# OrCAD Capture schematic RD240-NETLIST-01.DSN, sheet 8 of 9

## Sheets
8 2: size A3
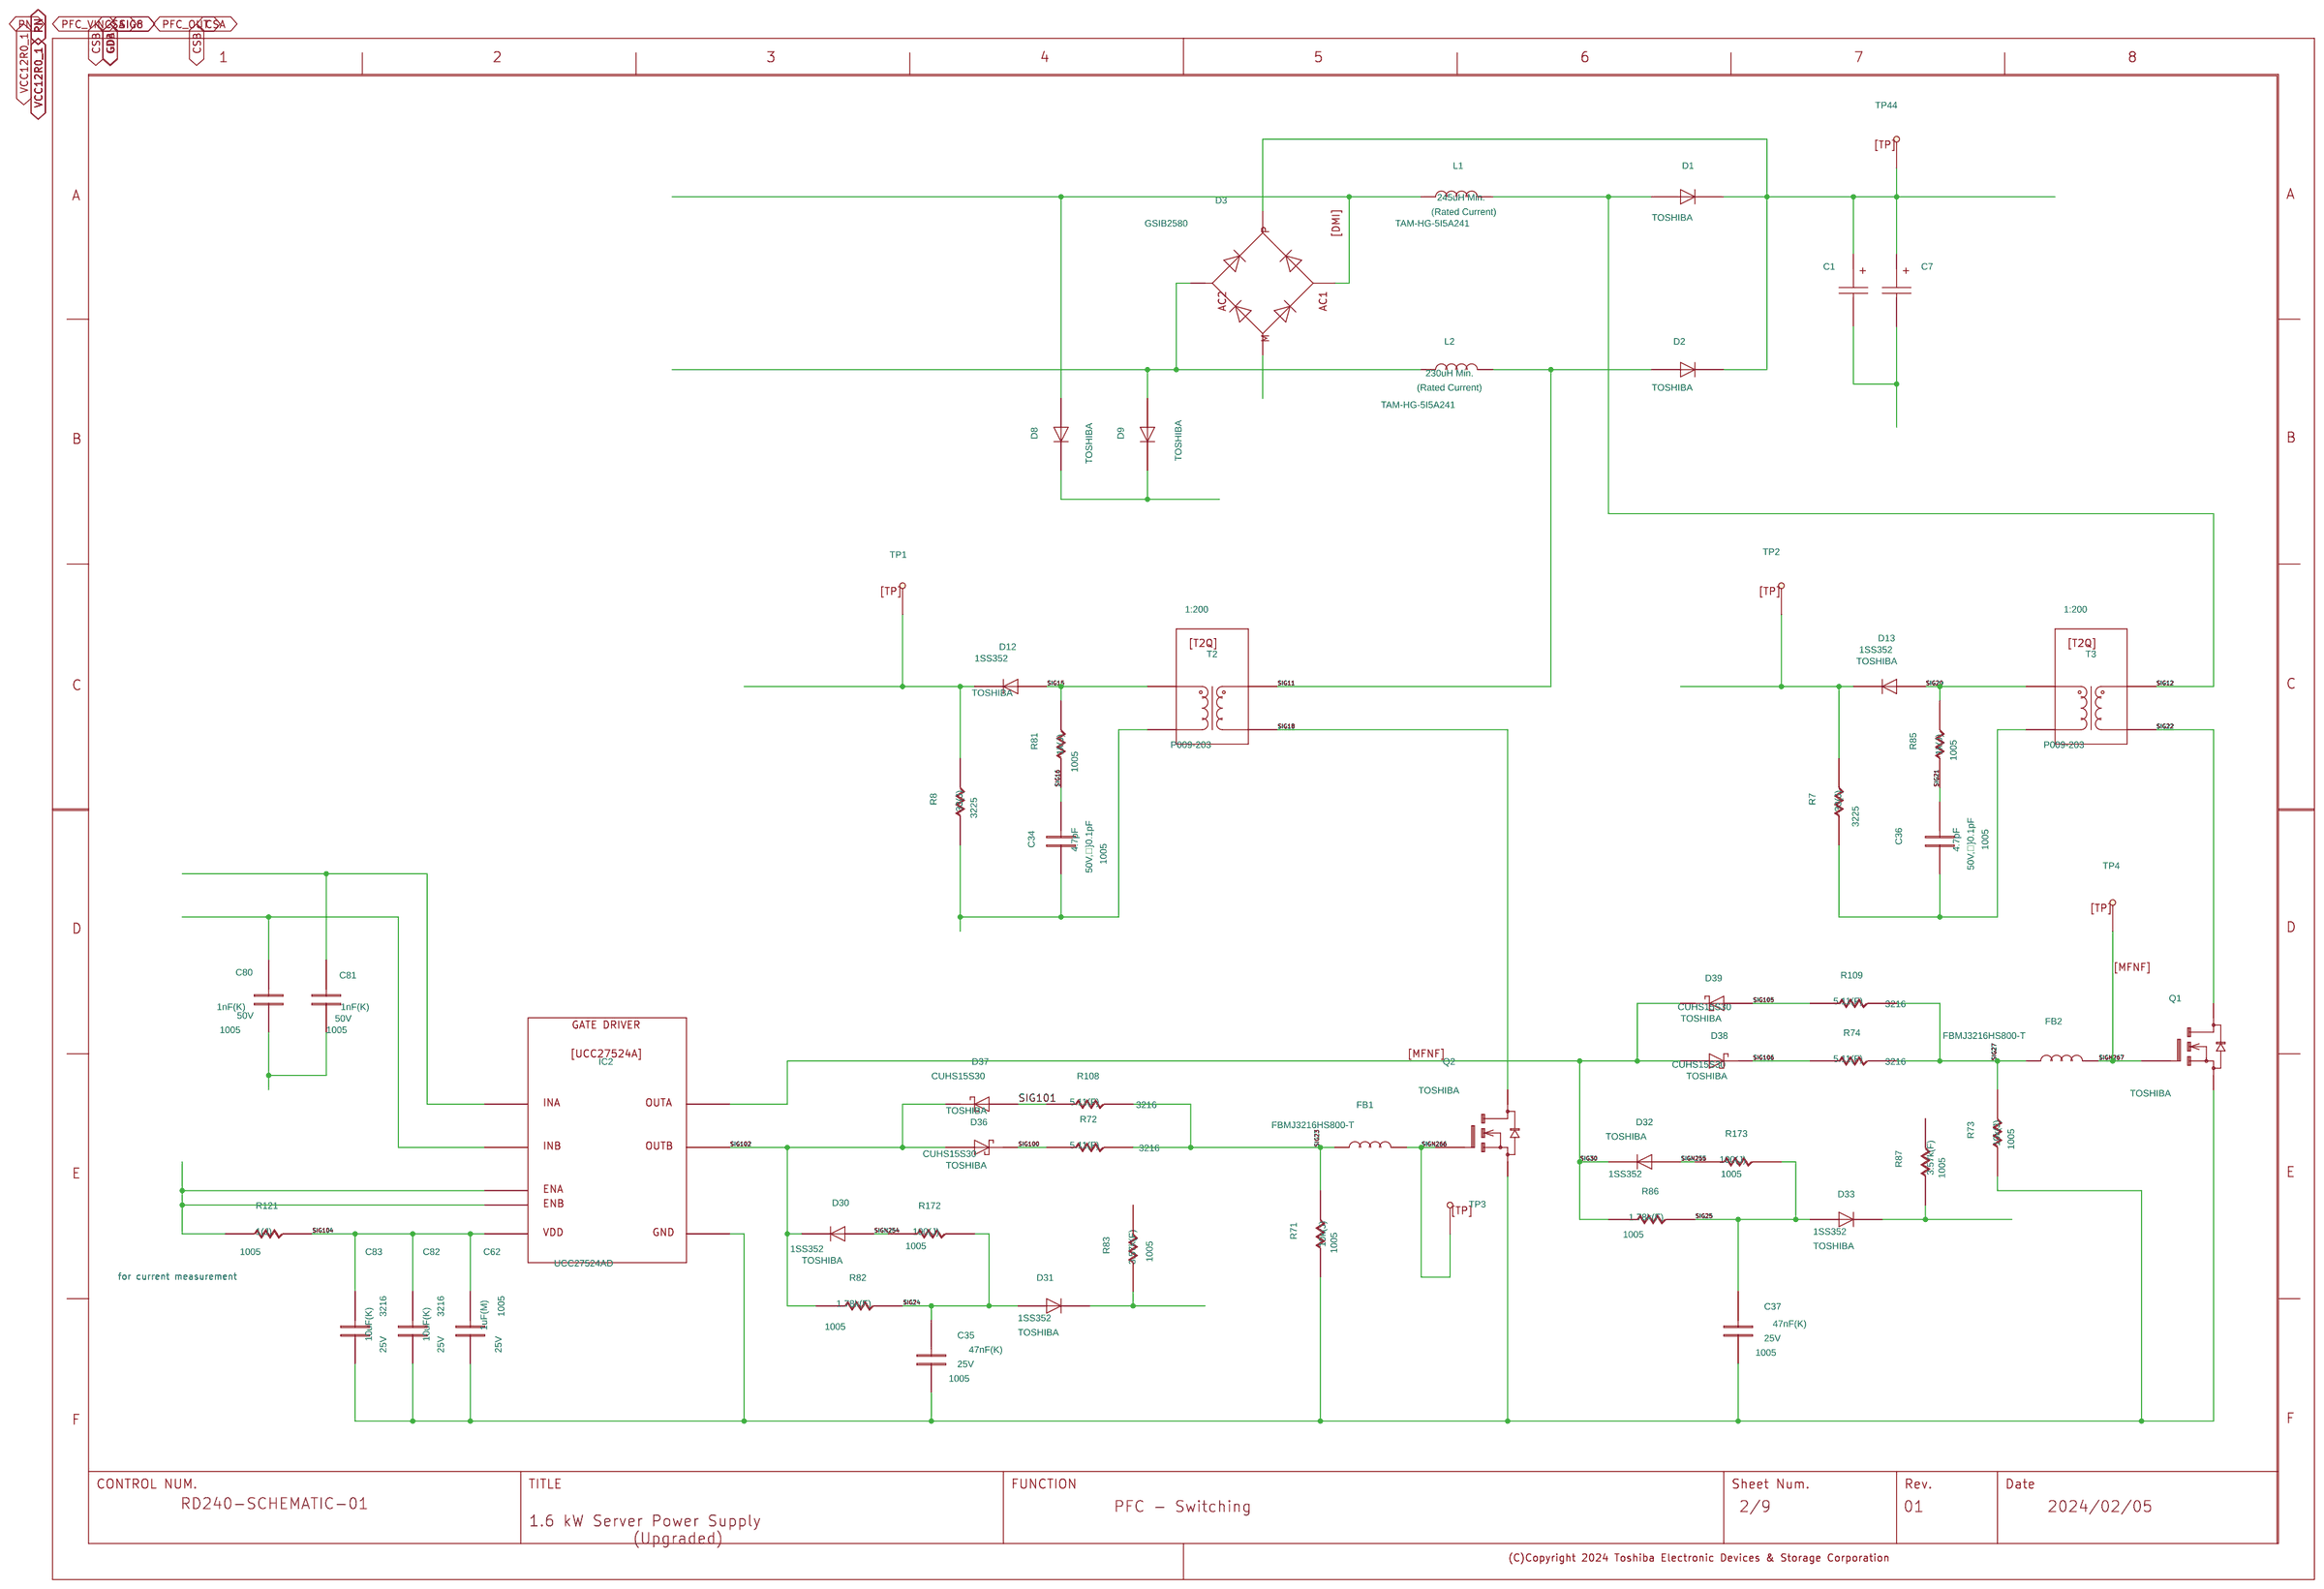
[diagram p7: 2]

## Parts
C1  EKHE451VSN331MQ35Z
C7  EKHE451VSN331MQ35Z
C34  C
C35  C
C36  C
C37  C
C62  C
C80  C
C81  C
C82  C
C83  C
D1  TRS8E65F
D2  TRS8E65F
D3  DMI
D8  CRG04A
D9  CRG04A
D12  D
D13  D
D30  D
D31  D
D32  D
D33  D
D36  CUHS15S30
D37  CUHS15S30
D38  CUHS15S30
D39  CUHS15S30
FB1  L
FB2  L
IC2  L27524
L1  L
L2  L
Q1  TK125N60Z1
Q2  TK125N60Z1
R7  R
R8  R
R71  R
R72  R
R73  R
R74  R
R81  R
R82  R
R83  R
R85  R
R86  R
R87  R
R108  R
R109  R
R121  R
R172  R
R173  R
T2  T2Q
T3  T2Q
TP1  TP
TP2  TP
TP3  TP
TP4  TP
TP44  TP
U?#7  WAKU_DEF100

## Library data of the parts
C1 = EKHE451VSN331MQ35Z: ADSCNVFLAG: ON; ALLGREEN: 1:ñO[; CAPACITANCETOLE: M; CDMASTERCADCELG: DC0209; CHIPSIZE: D35xL30; COMPCOMMENT: EKHS451VSN331MR30S; COMPONENTTYPE: 4; FNAPPROVALRESUG: 4:i; FNCANCELLATIONG: 0:Žg—p‰Â; FNENVIRONMANTRG: 2:Žg—p—L(ŠúŒÀ•t); FNLEADFREETHET1GT2GMCTH1: 9_N_N; GCOUNT: 1; ICX_PART_MODEL: CON_560U; INSTANCENAME: cmp239; MAKER: RUBYCON; MAXGCOUNT: 1; NOMINALCAPACITA: 560u; OUMECLASSIFICATION: ƒAƒ‹ƒ~“d‰ðƒRƒ“ƒfƒ“ƒT; OUMEMAKER: SIT ƒ‹ƒrƒRƒ“; OUMEMAKERKATAMEI: 250MXC560MB40; OUMEPARTTYPE: C; QUADMODEL: CON_560U; RATEDVOLTAGE: 250; SIZECODESMD: DIP; SQ_PART_MODEL: CON_560U
C7 = EKHE451VSN331MQ35Z: ADSCNVFLAG: ON; ALLGREEN: 1:ñO[; CAPACITANCETOLE: M; CDMASTERCADCELG: DC0209; CHIPSIZE: D35xL30; COMPCOMMENT: EKHS451VSN331MR30S; COMPONENTTYPE: 4; FNAPPROVALRESUG: 4:i; FNCANCELLATIONG: 0:Žg—p‰Â; FNENVIRONMANTRG: 2:Žg—p—L(ŠúŒÀ•t); FNLEADFREETHET1GT2GMCTH1: 9_N_N; GCOUNT: 1; ICX_PART_MODEL: CON_560U; INSTANCENAME: cmp238; MAKER: RUBYCON; MAXGCOUNT: 1; NOMINALCAPACITA: 560u; OUMECLASSIFICATION: ƒAƒ‹ƒ~“d‰ðƒRƒ“ƒfƒ“ƒT; OUMEMAKER: SIT ƒ‹ƒrƒRƒ“; OUMEMAKERKATAMEI: 250MXC560MB40; OUMEPARTTYPE: C; QUADMODEL: CON_560U; RATEDVOLTAGE: 250; SIZECODESMD: DIP; SQ_PART_MODEL: CON_560U
C34 = C: ADSMODELNAME: s_GRM1552C1H4R7CA01D; AUTHOR: sptcae13; CDMASTERCADCELG: KC0005; CHIPSIZE: 1005; COMP: PRT_52; COMPONENTTYPE: 4; DATE: 2024/01/31; FNLEADFREETHET1GT2GMCTH1: N_N_N; GCOUNT: 1; INSTANCENAME: cmp131; MAKER: MURATA; MAXGCOUNT: 1; NOMINALCAPACITA: 4.7p; OUMECLASSIFICATION: ƒZƒ‰ƒ~ƒbƒNƒRƒ“ƒfƒ“ƒT; OUMEMAKER: MRT ºc»ì; OUMEMAKERKATAMEI: GRM1552C1H4R7CA01D; PMPRODUCTSTYPEG: DME; QUADMODEL: CON_4.7P; RATEDVOLTAGE: 50; SAVECOUNT: 0; SIZECODESMD: 1005; TEMPCHARACTERI2: CH; TIME: 13:58:26; UPDATEDATE: 2024/01/31; UPDATETIME: 13:58:26; UPDATEUSER: sptcae13; VAL1: 4.7pF; VAL2: 50V,}0.1pF; VAL3: GRM1555C1H4R7BA01D
C35 = C: ADSCNVFLAG: ON; ADSCOMPONENTNAME: C_1005; ADSMODELNAME: s_GCM155R11C473KA01J; AUTHOR: sptcae13; CAPACITANCETOLE: K; CDMASTERCADCELG: KC0005; CHIPSIZE: 1005; COMP: PRT_52; COMPONENTTYPE: 4; DATE: 2024/01/31; FNLEADFREETHET1GT2GMCTH1: N_N_N; GCOUNT: 1; ICX_PART_MODEL: CON_47N; INSTANCENAME: cmp143; MAKER: MURATA; MAXGCOUNT: 1; NOMINALCAPACITA: 47n; OUMECLASSIFICATION: ƒZƒ‰ƒ~ƒbƒNƒRƒ“ƒfƒ“ƒT; OUMEMAKER: MRT ºc»ì; OUMEMAKERKATAMEI: GCM155R11C473KA01J; QUADMODEL: CON_47N; RATEDVOLTAGE: 16; SAVECOUNT: 0; SIZECODESMD: 1005; SQ_PART_MODEL: CON_47N; TEMPCHARACTERI2: R; TIME: 13:58:26; UPDATEDATE: 2024/01/31; UPDATETIME: 13:58:26; UPDATEUSER: sptcae13; VAL1: 47nF(K); VAL2: 25V; VAL3: GRM155R71E473KA88D
C36 = C: ADSMODELNAME: s_GRM1552C1H4R7CA01D; AUTHOR: sptcae13; CDMASTERCADCELG: KC0005; CHIPSIZE: 1005; COMP: PRT_52; COMPONENTTYPE: 4; DATE: 2024/01/31; FNLEADFREETHET1GT2GMCTH1: N_N_N; GCOUNT: 1; INSTANCENAME: cmp128; MAKER: MURATA; MAXGCOUNT: 1; NOMINALCAPACITA: 4.7p; OUMECLASSIFICATION: ƒZƒ‰ƒ~ƒbƒNƒRƒ“ƒfƒ“ƒT; OUMEMAKER: MRT ºc»ì; OUMEMAKERKATAMEI: GRM1552C1H4R7CA01D; PMPRODUCTSTYPEG: DME; QUADMODEL: CON_4.7P; RATEDVOLTAGE: 50; SAVECOUNT: 0; SIZECODESMD: 1005; TEMPCHARACTERI2: CH; TIME: 13:58:26; UPDATEDATE: 2024/01/31; UPDATETIME: 13:58:26; UPDATEUSER: sptcae13; VAL1: 4.7pF; VAL2: 50V,}0.1pF; VAL3: GRM1555C1H4R7BA01D
C37 = C: ADSMODELNAME: s_GCM155R11C473KA01J; AUTHOR: sptcae13; CAPACITANCETOLE: K; CDMASTERCADCELG: KC0005; CHIPSIZE: 1005; COMP: PRT_52; COMPONENTTYPE: 4; DATE: 2024/01/31; FNLEADFREETHET1GT2GMCTH1: N_N_N; GCOUNT: 1; INSTANCENAME: cmp142; MAKER: MURATA; MAXGCOUNT: 1; NOMINALCAPACITA: 47n; OUMECLASSIFICATION: ƒZƒ‰ƒ~ƒbƒNƒRƒ“ƒfƒ“ƒT; OUMEMAKER: MRT ºc»ì; OUMEMAKERKATAMEI: GCM155R11C473KA01J; QUADMODEL: CON_47N; RATEDVOLTAGE: 16; SAVECOUNT: 0; SIZECODESMD: 1005; TEMPCHARACTERI2: R; TIME: 13:58:26; UPDATEDATE: 2024/01/31; UPDATETIME: 13:58:26; UPDATEUSER: sptcae13; VAL1: 47nF(K); VAL2: 25V; VAL3: GRM155R71E473KA88D
C62 = C: ADSMODELNAME: s_C1005X5R1C105M050BC; AUTHOR: sptcae13; CAPACITANCETOLE: M; CDMASTERCADCELG: KC0005; CHIPSIZE: 1005; COMP: PRT_52; COMPONENTTYPE: 4; DATE: 2024/01/31; FNLEADFREETHET1GT2GMCTH1: N_N_N; GCOUNT: 1; INSTANCENAME: cmp219; MAKER: TDK; MAXGCOUNT: 1; NOMINALCAPACITA: 1u; OUMECLASSIFICATION: ƒZƒ‰ƒ~ƒbƒNƒRƒ“ƒfƒ“ƒT; OUMEMAKER: TDK ‚s‚c‚j; OUMEMAKERKATAMEI: C1005X5R1C105M050BC; QUADMODEL: CON_1U; RATEDVOLTAGE: 16; SAVECOUNT: 0; SIZECODESMD: 1005; TIME: 13:58:26; UPDATEDATE: 2024/01/31; UPDATETIME: 13:58:26; UPDATEUSER: sptcae13; VAL1: 1uF(M); VAL2: 25V; VAL3: C1005X5R1E105M050BC
C80 = C: ADSMODELNAME: s_UMK105BJ102KV_F; AUTHOR: sptcae13; CAPACITANCETOLE: K; CDMASTERCADCELG: KC0005; CHIPSIZE: 1005; COMP: PRT_52; COMPONENTTYPE: 4; DATE: 2024/01/31; FNLEADFREETHET1GT2GMCTH1: 2_0_N; GCOUNT: 1; INSTANCENAME: cmp200; MAKER: TDK; MAXGCOUNT: 1; NOMINALCAPACITA: 1n; OUMECLASSIFICATION: ƒZƒ‰ƒ~ƒbƒNƒRƒ“ƒfƒ“ƒT; OUMEMAKER: TYD ‘¾—z—U“d; OUMEMAKERKATAMEI: UMK105BJ102KV-F; PMPRODUCTSTYPEG: HD1-PC1; QUADMODEL: CON_1N; RATEDVOLTAGE: 50; SAVECOUNT: 0; SIZECODESMD: 1005; TEMPCHARACTERI2: B; TIME: 13:58:26; UPDATEDATE: 2024/01/31; UPDATETIME: 13:58:26; UPDATEUSER: sptcae13; VAL1: 1nF(K); VAL2: 50V; VAL3: UMK105BJ102KV-F
C81 = C: ADSMODELNAME: s_UMK105BJ102KV_F; AUTHOR: sptcae13; CAPACITANCETOLE: K; CDMASTERCADCELG: KC0005; CHIPSIZE: 1005; COMP: PRT_52; COMPONENTTYPE: 4; DATE: 2024/01/31; FNLEADFREETHET1GT2GMCTH1: 2_0_N; GCOUNT: 1; INSTANCENAME: cmp199; MAKER: TDK; MAXGCOUNT: 1; NOMINALCAPACITA: 1n; OUMECLASSIFICATION: ƒZƒ‰ƒ~ƒbƒNƒRƒ“ƒfƒ“ƒT; OUMEMAKER: TYD ‘¾—z—U“d; OUMEMAKERKATAMEI: UMK105BJ102KV-F; PMPRODUCTSTYPEG: HD1-PC1; QUADMODEL: CON_1N; RATEDVOLTAGE: 50; SAVECOUNT: 0; SIZECODESMD: 1005; TEMPCHARACTERI2: B; TIME: 13:58:26; UPDATEDATE: 2024/01/31; UPDATETIME: 13:58:26; UPDATEUSER: sptcae13; VAL1: 1nF(K); VAL2: 50V; VAL3: UMK105BJ102KV-F
C82 = C: ADSMODELNAME: s_TMK316LD106KL_T; AUTHOR: sptcae13; CAPACITANCETOLE: K; CDMASTERCADCELG: KC0014; CHIPSIZE: 3216; COMP: PRT_46; COMPONENTTYPE: 4; DATE: 2024/01/31; FNLEADFREETHET1GT2GMCTH1: N_N_N; GCOUNT: 1; INSTANCENAME: cmp220; MAKER: TAIYO YUDEN; MAXGCOUNT: 1; NOMINALCAPACITA: 10u; OUMECLASSIFICATION: ƒZƒ‰ƒ~ƒbƒNƒRƒ“ƒfƒ“ƒT; OUMEMAKER: TYD ‘¾—z—U“d; OUMEMAKERKATAMEI: TMK316LD106KL-T; QUADMODEL: CON_10U; RATEDVOLTAGE: 25; SAVECOUNT: 0; SIZECODESMD: 3216; TIME: 13:58:26; UPDATEDATE: 2024/01/31; UPDATETIME: 13:58:26; UPDATEUSER: sptcae13; VAL1: 10uF(K); VAL2: 25V; VAL3: TMK316BJ106KL-T
C83 = C: ADSMODELNAME: s_TMK316LD106KL_T; AUTHOR: sptcae13; CAPACITANCETOLE: K; CDMASTERCADCELG: KC0014; CHIPSIZE: 3216; COMP: PRT_46; COMPONENTTYPE: 4; DATE: 2024/01/31; FNLEADFREETHET1GT2GMCTH1: N_N_N; GCOUNT: 1; INSTANCENAME: cmp221; MAKER: TAIYO YUDEN; MAXGCOUNT: 1; NOMINALCAPACITA: 10u; OUMECLASSIFICATION: ƒZƒ‰ƒ~ƒbƒNƒRƒ“ƒfƒ“ƒT; OUMEMAKER: TYD ‘¾—z—U“d; OUMEMAKERKATAMEI: TMK316LD106KL-T; QUADMODEL: CON_10U; RATEDVOLTAGE: 25; SAVECOUNT: 0; SIZECODESMD: 3216; TIME: 13:58:26; UPDATEDATE: 2024/01/31; UPDATETIME: 13:58:26; UPDATEUSER: sptcae13; VAL1: 10uF(K); VAL2: 25V; VAL3: TMK316BJ106KL-T
D1 = TRS8E65F: ADSMODELNAME: s_1N4148; CDMASTERCADCELG: DCR071; COMPCOMMENT: ãÖFTRS6E65H; COMPONENTTYPE: 4; FNLEADFREETHET1GT2GMCTH1: N_N_N; FORWARDVOLTAGEM: 0; GCOUNT: 1; INSTANCENAME: cmp22; MAKER: TOSHIBA; MAXAVERAGEFORWA: 0; MAXGCOUNT: 1; MAXREPETITIVEPE: 0; MAXREVERSEVOLTA: 100; MOUNTINGFORMSMD: DIP; OUMECLASSIFICATION: ¬M_CI[h; OUMEMAKER: ROH [; OUMEMAKERKATAMEI: 1N4148; OUMEPARTTYPE: D; PEAKFORWARDVOLT: 0; REVERSECURRENT: 0; USERCOMPTEXT1: TRS6E65H; USERCOMPTEXT3: TOSHIBA; ZENERVOLTAGEMAX: 0; ZENERVOLTAGEMIN: 0
D2 = TRS8E65F: ADSMODELNAME: s_1N4148; CDMASTERCADCELG: DCR071; COMPCOMMENT: ãÖFTRS6E65H; COMPONENTTYPE: 4; FNLEADFREETHET1GT2GMCTH1: N_N_N; FORWARDVOLTAGEM: 0; GCOUNT: 1; INSTANCENAME: cmp23; MAKER: TOSHIBA; MAXAVERAGEFORWA: 0; MAXGCOUNT: 1; MAXREPETITIVEPE: 0; MAXREVERSEVOLTA: 100; MOUNTINGFORMSMD: DIP; OUMECLASSIFICATION: ¬M_CI[h; OUMEMAKER: ROH [; OUMEMAKERKATAMEI: 1N4148; OUMEPARTTYPE: D; PEAKFORWARDVOLT: 0; REVERSECURRENT: 0; USERCOMPTEXT1: TRS6E65H; USERCOMPTEXT3: TOSHIBA; ZENERVOLTAGEMAX: 0; ZENERVOLTAGEMIN: 0
D3 = DMI: ADSMODELNAME: s_D1UBA80_EMBEDED; AUTHOR: sptcae13; CDMASTERCADCELG: MMK0161; COMP: PRT_53; COMPONENTTYPE: 4; DATE: 2024/01/31; FNLEADFREETHET1GT2GMCTH1: N_N_N; FORWARDVOLTAGEM: 0; GCOUNT: 1; INSTANCENAME: cmp107; MAKER: VISHAY; MAXAVERAGEFORWA: 800m; MAXGCOUNT: 1; MAXREPETITIVEPE: 800; MAXREVERSEVOLTA: 0; MOUNTINGFORMSMD: SMD; OUMECLASSIFICATION: êÊ®¬fq; OUMEMAKER: SDG Vd³HÆ; OUMEMAKERKATAMEI: D1UBA80_EMBEDED; OUMEPARTTYPE: D; PEAKFORWARDVOLT: 950m; REVERSECURRENT: 10u; TIME: 13:58:25; UPDATEDATE: 2024/01/31; UPDATETIME: 13:58:25; UPDATEUSER: sptcae13; VAL3: GSIB2580; ZENERVOLTAGEMAX: 0; ZENERVOLTAGEMIN: 0
D8 = CRG04A: ADSMODELNAME: s_CRS01_TE85R_Q_; ALLGREEN: N:¢²¸; CDMASTERCADCELG: MMK0167; COMPONENTTYPE: 4; FNAPPROVALRESUG: 5:bè(KR[h); FNCANCELLATIONG: 0:Žg—p‰Â; FNENVIRONMANTRG: N:¢²¸; FNLEADFREETHET1GT2GMCTH1: N_N_N; FORWARDVOLTAGEM: 0; GCOUNT: 1; INSTANCENAME: cmp71; MAKER: TOSHIBA; MAXAVERAGEFORWA: 1; MAXGCOUNT: 1; MAXREPETITIVEPE: 30; MAXREVERSEVOLTA: 0; MOUNTINGFORMSMD: SMD; OUMECLASSIFICATION: ¬p®¬fq/VbgLoA_CI[h; OUMEMAKER: TSB “ŒŽÅ; OUMEMAKERKATAMEI: CRS01(TE85R,Q); OUMEPARTTYPE: D; PEAKFORWARDVOLT: 360m; REVERSECURRENT: 1.5m; USERCOMPTEXT3: TOSHIBA; ZENERVOLTAGEMAX: 0; ZENERVOLTAGEMIN: 0
D9 = CRG04A: ADSMODELNAME: s_CRS01_TE85R_Q_; ALLGREEN: N:¢²¸; CDMASTERCADCELG: MMK0167; COMPONENTTYPE: 4; FNAPPROVALRESUG: 5:bè(KR[h); FNCANCELLATIONG: 0:Žg—p‰Â; FNENVIRONMANTRG: N:¢²¸; FNLEADFREETHET1GT2GMCTH1: N_N_N; FORWARDVOLTAGEM: 0; GCOUNT: 1; INSTANCENAME: cmp72; MAKER: TOSHIBA; MAXAVERAGEFORWA: 1; MAXGCOUNT: 1; MAXREPETITIVEPE: 30; MAXREVERSEVOLTA: 0; MOUNTINGFORMSMD: SMD; OUMECLASSIFICATION: ¬p®¬fq/VbgLoA_CI[h; OUMEMAKER: TSB “ŒŽÅ; OUMEMAKERKATAMEI: CRS01(TE85R,Q); OUMEPARTTYPE: D; PEAKFORWARDVOLT: 360m; REVERSECURRENT: 1.5m; USERCOMPTEXT3: TOSHIBA; ZENERVOLTAGEMAX: 0; ZENERVOLTAGEMIN: 0
D12 = D: ADSMODELNAME: s_1SS352_TPH3_F_1_1E1A; AUTHOR: sptcae13; CDMASTERCADCELG: D81022; COMP: PRT_27; COMPONENTTYPE: 4; DATE: 2024/01/31; FNLEADFREETHET1GT2GMCTH1: N_N_N; FORWARDVOLTAGEM: 0; GCOUNT: 1; INSTANCENAME: cmp76; MAKER: TOSHIBA; MAXAVERAGEFORWA: 0; MAXGCOUNT: 1; MAXREPETITIVEPE: 0; MAXREVERSEVOLTA: 80; MOUNTINGFORMSMD: SMD; OUMECLASSIFICATION: ¬M_CI[h; OUMEMAKER: TSB “ŒŽÅ; OUMEMAKERKATAMEI: 1SS352(TPH3,F)1-1E1A; PEAKFORWARDVOLT: 0; REVERSECURRENT: 0; TIME: 13:58:26; UPDATEDATE: 2024/01/31; UPDATETIME: 13:58:26; UPDATEUSER: sptcae13; USERCOMPTEXT3: TOSHIBA; VAL3: 1SS352; ZENERVOLTAGEMAX: 0; ZENERVOLTAGEMIN: 0
D13 = D: ADSMODELNAME: s_1SS352_TPH3_F_1_1E1A; AUTHOR: sptcae13; CDMASTERCADCELG: D81022; COMP: PRT_27; COMPONENTTYPE: 4; DATE: 2024/01/31; FNLEADFREETHET1GT2GMCTH1: N_N_N; FORWARDVOLTAGEM: 0; GCOUNT: 1; INSTANCENAME: cmp77; MAKER: TOSHIBA; MAXAVERAGEFORWA: 0; MAXGCOUNT: 1; MAXREPETITIVEPE: 0; MAXREVERSEVOLTA: 80; MOUNTINGFORMSMD: SMD; OUMECLASSIFICATION: ¬M_CI[h; OUMEMAKER: TSB “ŒŽÅ; OUMEMAKERKATAMEI: 1SS352(TPH3,F)1-1E1A; PEAKFORWARDVOLT: 0; REVERSECURRENT: 0; TIME: 13:58:26; UPDATEDATE: 2024/01/31; UPDATETIME: 13:58:26; UPDATEUSER: sptcae13; USERCOMPTEXT3: TOSHIBA; VAL3: 1SS352; ZENERVOLTAGEMAX: 0; ZENERVOLTAGEMIN: 0
D30 = D: ADSMODELNAME: s_1SS352_TPH3_F_1_1E1A; AUTHOR: sptcae13; CDMASTERCADCELG: D81022; COMP: PRT_27; COMPONENTTYPE: 4; DATE: 2024/01/31; FNLEADFREETHET1GT2GMCTH1: N_N_N; FORWARDVOLTAGEM: 0; GCOUNT: 1; INSTANCENAME: cmp80; MAKER: TOSHIBA; MAXAVERAGEFORWA: 0; MAXGCOUNT: 1; MAXREPETITIVEPE: 0; MAXREVERSEVOLTA: 80; MOUNTINGFORMSMD: SMD; OUMECLASSIFICATION: ¬M_CI[h; OUMEMAKER: TSB “ŒŽÅ; OUMEMAKERKATAMEI: 1SS352(TPH3,F)1-1E1A; PEAKFORWARDVOLT: 0; REVERSECURRENT: 0; TIME: 13:58:26; UPDATEDATE: 2024/01/31; UPDATETIME: 13:58:26; UPDATEUSER: sptcae13; USERCOMPTEXT3: TOSHIBA; VAL3: 1SS352; ZENERVOLTAGEMAX: 0; ZENERVOLTAGEMIN: 0
D31 = D: ADSCNVFLAG: ON; ADSCOMPONENTNAME: D_D; ADSMODELNAME: s_1SS352_TPH3_F_1_1E1A; AUTHOR: sptcae13; CDMASTERCADCELG: D81022; COMP: PRT_27; COMPONENTTYPE: 4; DATE: 2024/01/31; FNLEADFREETHET1GT2GMCTH1: N_N_N; FORWARDVOLTAGEM: 0; GCOUNT: 1; INSTANCENAME: cmp81; MAKER: TOSHIBA; MAXAVERAGEFORWA: 0; MAXGCOUNT: 1; MAXREPETITIVEPE: 0; MAXREVERSEVOLTA: 80; MOUNTINGFORMSMD: SMD; OUMECLASSIFICATION: ¬M_CI[h; OUMEMAKER: TSB “ŒŽÅ; OUMEMAKERKATAMEI: 1SS352(TPH3,F)1-1E1A; PEAKFORWARDVOLT: 0; REVERSECURRENT: 0; TIME: 13:58:26; UPDATEDATE: 2024/01/31; UPDATETIME: 13:58:26; UPDATEUSER: sptcae13; USERCOMPTEXT3: TOSHIBA; VAL3: 1SS352; ZENERVOLTAGEMAX: 0; ZENERVOLTAGEMIN: 0
D32 = D: ADSMODELNAME: s_1SS352_TPH3_F_1_1E1A; AUTHOR: sptcae13; CDMASTERCADCELG: D81022; COMP: PRT_27; COMPONENTTYPE: 4; DATE: 2024/01/31; FNLEADFREETHET1GT2GMCTH1: N_N_N; FORWARDVOLTAGEM: 0; GCOUNT: 1; INSTANCENAME: cmp86; MAKER: TOSHIBA; MAXAVERAGEFORWA: 0; MAXGCOUNT: 1; MAXREPETITIVEPE: 0; MAXREVERSEVOLTA: 80; MOUNTINGFORMSMD: SMD; OUMECLASSIFICATION: ¬M_CI[h; OUMEMAKER: TSB “ŒŽÅ; OUMEMAKERKATAMEI: 1SS352(TPH3,F)1-1E1A; PEAKFORWARDVOLT: 0; REVERSECURRENT: 0; TIME: 13:58:26; UPDATEDATE: 2024/01/31; UPDATETIME: 13:58:26; UPDATEUSER: sptcae13; USERCOMPTEXT3: TOSHIBA; VAL3: 1SS352; ZENERVOLTAGEMAX: 0; ZENERVOLTAGEMIN: 0
D33 = D: ADSMODELNAME: s_1SS352_TPH3_F_1_1E1A; AUTHOR: sptcae13; CDMASTERCADCELG: D81022; COMP: PRT_27; COMPONENTTYPE: 4; DATE: 2024/01/31; FNLEADFREETHET1GT2GMCTH1: N_N_N; FORWARDVOLTAGEM: 0; GCOUNT: 1; INSTANCENAME: cmp87; MAKER: TOSHIBA; MAXAVERAGEFORWA: 0; MAXGCOUNT: 1; MAXREPETITIVEPE: 0; MAXREVERSEVOLTA: 80; MOUNTINGFORMSMD: SMD; OUMECLASSIFICATION: ¬M_CI[h; OUMEMAKER: TSB “ŒŽÅ; OUMEMAKERKATAMEI: 1SS352(TPH3,F)1-1E1A; PEAKFORWARDVOLT: 0; REVERSECURRENT: 0; TIME: 13:58:26; UPDATEDATE: 2024/01/31; UPDATETIME: 13:58:26; UPDATEUSER: sptcae13; USERCOMPTEXT3: TOSHIBA; VAL3: 1SS352; ZENERVOLTAGEMAX: 0; ZENERVOLTAGEMIN: 0
D36 = CUHS15S30: ADSMODELNAME: s_CUS01_TE85L_Q_; CDMASTERCADCELG: MM0042; COMPONENTTYPE: 4; FNLEADFREETHET1GT2GMCTH1: 2_0_N; FORWARDVOLTAGEM: 0; GCOUNT: 1; INSTANCENAME: cmp111; MAKER: TOSHIBA; MAXAVERAGEFORWA: 1; MAXGCOUNT: 1; MAXREPETITIVEPE: 30; MAXREVERSEVOLTA: 0; MOUNTINGFORMSMD: SMD; OUMECLASSIFICATION: ¬p®¬fq/VbgLoA_CI[h; OUMEMAKER: TSB “ŒŽÅ; OUMEMAKERKATAMEI: CUS01(TE85L,Q); OUMEPARTTYPE: D; PEAKFORWARDVOLT: 370m; PMPRODUCTSTYPEG: PC1; REVERSECURRENT: 500u; USERCOMPTEXT3: TOSHIBA; ZENERVOLTAGEMAX: 0; ZENERVOLTAGEMIN: 0
D37 = CUHS15S30: ADSMODELNAME: s_CUS01_TE85L_Q_; CDMASTERCADCELG: MM0042; COMPONENTTYPE: 4; FNLEADFREETHET1GT2GMCTH1: 2_0_N; FORWARDVOLTAGEM: 0; GCOUNT: 1; INSTANCENAME: cmp112; MAKER: TOSHIBA; MAXAVERAGEFORWA: 1; MAXGCOUNT: 1; MAXREPETITIVEPE: 30; MAXREVERSEVOLTA: 0; MOUNTINGFORMSMD: SMD; OUMECLASSIFICATION: ¬p®¬fq/VbgLoA_CI[h; OUMEMAKER: TSB “ŒŽÅ; OUMEMAKERKATAMEI: CUS01(TE85L,Q); OUMEPARTTYPE: D; PEAKFORWARDVOLT: 370m; PMPRODUCTSTYPEG: PC1; REVERSECURRENT: 500u; USERCOMPTEXT3: TOSHIBA; ZENERVOLTAGEMAX: 0; ZENERVOLTAGEMIN: 0
D38 = CUHS15S30: ADSMODELNAME: s_CUS01_TE85L_Q_; CDMASTERCADCELG: MM0042; COMPONENTTYPE: 4; FNLEADFREETHET1GT2GMCTH1: 2_0_N; FORWARDVOLTAGEM: 0; GCOUNT: 1; INSTANCENAME: cmp109; MAKER: TOSHIBA; MAXAVERAGEFORWA: 1; MAXGCOUNT: 1; MAXREPETITIVEPE: 30; MAXREVERSEVOLTA: 0; MOUNTINGFORMSMD: SMD; OUMECLASSIFICATION: ¬p®¬fq/VbgLoA_CI[h; OUMEMAKER: TSB “ŒŽÅ; OUMEMAKERKATAMEI: CUS01(TE85L,Q); OUMEPARTTYPE: D; PEAKFORWARDVOLT: 370m; PMPRODUCTSTYPEG: PC1; REVERSECURRENT: 500u; USERCOMPTEXT3: TOSHIBA; ZENERVOLTAGEMAX: 0; ZENERVOLTAGEMIN: 0
D39 = CUHS15S30: ADSMODELNAME: s_CUS01_TE85L_Q_; CDMASTERCADCELG: MM0042; COMPONENTTYPE: 4; FNLEADFREETHET1GT2GMCTH1: 2_0_N; FORWARDVOLTAGEM: 0; GCOUNT: 1; INSTANCENAME: cmp110; MAKER: TOSHIBA; MAXAVERAGEFORWA: 1; MAXGCOUNT: 1; MAXREPETITIVEPE: 30; MAXREVERSEVOLTA: 0; MOUNTINGFORMSMD: SMD; OUMECLASSIFICATION: ¬p®¬fq/VbgLoA_CI[h; OUMEMAKER: TSB “ŒŽÅ; OUMEMAKERKATAMEI: CUS01(TE85L,Q); OUMEPARTTYPE: D; PEAKFORWARDVOLT: 370m; PMPRODUCTSTYPEG: PC1; REVERSECURRENT: 500u; USERCOMPTEXT3: TOSHIBA; ZENERVOLTAGEMAX: 0; ZENERVOLTAGEMIN: 0
FB1 = L: AUTHOR: sptcae13; COMP: PRT_30; COMPONENTTYPE: 4; DATE: 2024/01/31; INSTANCENAME: cmp171; MAKER: TAIYO YUDEN; SAVECOUNT: 0; TIME: 13:58:25; UPDATEDATE: 2024/01/31; UPDATETIME: 13:58:25; UPDATEUSER: sptcae13; VAL3: FBMJ3216HS800-T
FB2 = L: AUTHOR: sptcae13; COMP: PRT_30; COMPONENTTYPE: 4; DATE: 2024/01/31; INSTANCENAME: cmp173; MAKER: TAIYO YUDEN; SAVECOUNT: 0; TIME: 13:58:25; UPDATEDATE: 2024/01/31; UPDATETIME: 13:58:25; UPDATEUSER: sptcae13; VAL3: FBMJ3216HS800-T
IC2 = L27524: COMP: PRT_63; COMPONENTTYPE: 4; INSTANCENAME: cmp18; MAKER: TEXAS; VAL3: UCC27524AD
L1 = L: AUTHOR: sptcae13; COMP: PRT_41; COMPONENTTYPE: 4; DATE: 2024/01/31; GCOUNT: 1; INDUCTANCEMAX: 0; INDUCTANCEMIN: 0; INSTANCENAME: cmp20; MAKER: TMP; MAXGCOUNT: 1; MOUNTINGFORMSMD: DIP; NOMINALINDUCTA1: 100u; NOMINALINDUCTA2: K; SAVECOUNT: 0; TIME: 13:58:25; UPDATEDATE: 2024/01/31; UPDATETIME: 13:58:25; UPDATEUSER: sptcae13; VAL1: 245uH Min.; VAL2: (Rated Current); VAL3: TAM-HG-5I5A241
L2 = L: AUTHOR: sptcae13; COMP: PRT_41; COMPONENTTYPE: 4; DATE: 2024/01/31; GCOUNT: 1; INDUCTANCEMAX: 0; INDUCTANCEMIN: 0; INSTANCENAME: cmp21; MAKER: TMP; MAXGCOUNT: 1; MOUNTINGFORMSMD: DIP; NOMINALINDUCTA1: 100u; NOMINALINDUCTA2: K; SAVECOUNT: 0; TIME: 13:58:25; UPDATEDATE: 2024/01/31; UPDATETIME: 13:58:25; UPDATEUSER: sptcae13; VAL1: 230uH Min.; VAL2: (Rated Current); VAL3: TAM-HG-5I5A241
Q1 = TK125N60Z1: ADSMODELNAME: s_TK040N65Z; ALLGREEN: N:¢²¸; CDMASTERCADCELG: RDP1002; COMPONENTTYPE: 4; FNAPPROVALRESUG: 5:bè(KR[h); FNCANCELLATIONG: 0:Žg—p‰Â; FNENVIRONMANTRG: N:¢²¸; FNLEADFREETHET1GT2GMCTH1: N_N_N; GCOUNT: 1; INSTANCENAME: cmp43; MAKER: TOSHIBA; MAXCBVOLTAGE: 0; MAXCEVOLTAGE: 0; MAXCOLLECTORCUR: 0; MAXDRAINCURRENT: 57; MAXDSVOLTAGE: 650; MAXEBVOLTAGE: 0; MAXGATECURRENT: 0; MAXGCOUNT: 1; MAXGDVOLTAGE: 0; MAXGSVOLTAGE: 30; MOUNTINGFORMSMD: DIP; OUMECLASSIFICATION: Nƒ`ƒƒƒ“ƒlƒ‹MOS-FET; OUMEMAKER: TSB “ŒŽÅ; OUMEMAKERKATAMEI: TK040N65Z; OUMEPARTTYPE: Q; USERCOMPTEXT3: TOSHIBA
Q2 = TK125N60Z1: ADSMODELNAME: s_TK040N65Z; ALLGREEN: N:¢²¸; CDMASTERCADCELG: RDP1002; COMPONENTTYPE: 4; FNAPPROVALRESUG: 5:bè(KR[h); FNCANCELLATIONG: 0:Žg—p‰Â; FNENVIRONMANTRG: N:¢²¸; FNLEADFREETHET1GT2GMCTH1: N_N_N; GCOUNT: 1; INSTANCENAME: cmp35; MAKER: TOSHIBA; MAXCBVOLTAGE: 0; MAXCEVOLTAGE: 0; MAXCOLLECTORCUR: 0; MAXDRAINCURRENT: 57; MAXDSVOLTAGE: 650; MAXEBVOLTAGE: 0; MAXGATECURRENT: 0; MAXGCOUNT: 1; MAXGDVOLTAGE: 0; MAXGSVOLTAGE: 30; MOUNTINGFORMSMD: DIP; OUMECLASSIFICATION: Nƒ`ƒƒƒ“ƒlƒ‹MOS-FET; OUMEMAKER: TSB “ŒŽÅ; OUMEMAKERKATAMEI: TK040N65Z; OUMEPARTTYPE: Q; USERCOMPTEXT3: TOSHIBA
R7 = R: CHIPSIZE: 3225; COMPONENTTYPE: 4; INSTANCENAME: cmp156; MAKER: PANASONIC; SAVEAREA0: -588,-4192,15498,7584; SAVECOUNT: 0; SIZECODESMD: 3225; UPDATETIME: 09:21:07; VAL1: 33(J); VAL2: 500mW; VAL3: ERJ-14YJ330U
R8 = R: CHIPSIZE: 3225; COMPONENTTYPE: 4; INSTANCENAME: cmp158; MAKER: PANASONIC; SAVEAREA0: -588,-4192,15498,7584; SAVECOUNT: 0; SIZECODESMD: 3225; UPDATETIME: 09:21:07; VAL1: 33(J); VAL2: 500mW; VAL3: ERJ-14YJ330U
R71 = R: ADSMODELNAME: s_RC0402FR_071KL; ALLGREEN: 0:O[; CDMASTERCADCELG: KC0005; CHIPSIZE: 1608; COMPONENTTYPE: 4; FNAPPROVALRESUG: B:i(GREEN); FNCANCELLATIONG: 0:Žg—p‰Â; FNENVIRONMANTRG: 1:gpL(K§ÎÛO); FNLEADFREETHET1GT2GMCTH1: 2_2_N; GANSWERREV: 8; GCOUNT: 1; INSTANCENAME: cmp225; MAKER: KOA; MAXGCOUNT: 1; MOUNTINGFORMSMD: SMD; NOMINALRESISTAN: 1K; OUMECLASSIFICATION: \ÊÀpÅèïRí; OUMEMAKER: YGO ƒ„ƒQƒI; OUMEMAKERKATAMEI: RC0402FR-071KL; PMPRODUCTSTYPEG: HD1; POWERRATING: 63m; QUADMODEL: RES_1K; RESISTANCETOLER: F; SAVECOUNT: 0; SIZECODESMD: 1005; VAL1: 10k(J); VAL2: 63mW; VAL3: RK73B1ERTTP103J
R72 = R: ADSMODELNAME: s_RK73H2BTTD6R80F; CDMASTERCADCELG: DR901A; CHIPSIZE: 3216; COMPONENTTYPE: 4; FNLEADFREETHET1GT2GMCTH1: 3_1_N; GCOUNT: 1; INSTANCENAME: cmp223; MAKER: BOURNS; MAXGCOUNT: 1; MOUNTINGFORMSMD: SMD; NOMINALRESISTAN: 6.8; OUMECLASSIFICATION: \ÊÀpÅèïRí; OUMEMAKER: KOA R[A; OUMEMAKERKATAMEI: RK73H2BTTD6R80F; POWERRATING: 125m; QUADMODEL: RES_6.8; RESISTANCETOLER: F; SAVEAREA0: -588,-4192,15498,7584; SAVECOUNT: 0; SIZECODESMD: 3216; UPDATETIME: 09:21:07; VAL1: 5.11(F); VAL2: 500mW; VAL3: CRM1206-FX-5R11ELF
R73 = R: ADSMODELNAME: s_RC0402FR_071KL; ALLGREEN: 0:O[; CDMASTERCADCELG: KC0005; CHIPSIZE: 1608; COMPONENTTYPE: 4; FNAPPROVALRESUG: B:i(GREEN); FNCANCELLATIONG: 0:Žg—p‰Â; FNENVIRONMANTRG: 1:gpL(K§ÎÛO); FNLEADFREETHET1GT2GMCTH1: 2_2_N; GANSWERREV: 8; GCOUNT: 1; INSTANCENAME: cmp229; MAKER: KOA; MAXGCOUNT: 1; MOUNTINGFORMSMD: SMD; NOMINALRESISTAN: 1K; OUMECLASSIFICATION: \ÊÀpÅèïRí; OUMEMAKER: YGO ƒ„ƒQƒI; OUMEMAKERKATAMEI: RC0402FR-071KL; PMPRODUCTSTYPEG: HD1; POWERRATING: 63m; QUADMODEL: RES_1K; RESISTANCETOLER: F; SAVEAREA0: -588,-4192,15498,7584; SAVECOUNT: 0; SIZECODESMD: 1005; UPDATETIME: 09:21:07; VAL1: 10k(J); VAL2: 63mW; VAL3: RK73B1ERTTP103J
R74 = R: ADSMODELNAME: s_RK73H2BTTD6R80F; CDMASTERCADCELG: DR901A; CHIPSIZE: 3216; COMPONENTTYPE: 4; FNLEADFREETHET1GT2GMCTH1: 3_1_N; GCOUNT: 1; INSTANCENAME: cmp226; MAKER: BOURNS; MAXGCOUNT: 1; MOUNTINGFORMSMD: SMD; NOMINALRESISTAN: 6.8; OUMECLASSIFICATION: \ÊÀpÅèïRí; OUMEMAKER: KOA R[A; OUMEMAKERKATAMEI: RK73H2BTTD6R80F; POWERRATING: 125m; QUADMODEL: RES_6.8; RESISTANCETOLER: F; SAVEAREA0: -588,-4192,15498,7584; SAVECOUNT: 0; SIZECODESMD: 3216; UPDATETIME: 09:21:07; VAL1: 5.11(F); VAL2: 500mW; VAL3: CRM1206-FX-5R11ELF
R81 = R: ADSMODELNAME: s_RC0402FR_071KL; ALLGREEN: 0:O[; CDMASTERCADCELG: KC0005; CHIPSIZE: 1608; COMPONENTTYPE: 4; FNAPPROVALRESUG: B:i(GREEN); FNCANCELLATIONG: 0:Žg—p‰Â; FNENVIRONMANTRG: 1:gpL(K§ÎÛO); FNLEADFREETHET1GT2GMCTH1: 2_2_N; GANSWERREV: 8; GCOUNT: 1; INSTANCENAME: cmp217; MAKER: KOA; MAXGCOUNT: 1; MOUNTINGFORMSMD: SMD; NOMINALRESISTAN: 1K; OUMECLASSIFICATION: \ÊÀpÅèïRí; OUMEMAKER: YGO ƒ„ƒQƒI; OUMEMAKERKATAMEI: RC0402FR-071KL; PMPRODUCTSTYPEG: HD1; POWERRATING: 63m; QUADMODEL: RES_1K; RESISTANCETOLER: F; SAVEAREA0: -588,-4192,15498,7584; SAVECOUNT: 0; SIZECODESMD: 1005; UPDATETIME: 09:21:07; VAL1: 1k(J); VAL2: 63mW; VAL3: RK73K1ETP102J
R82 = R: ADSMODELNAME: s_RC0402FR_071KL; ALLGREEN: 0:O[; CDMASTERCADCELG: KC0005; CHIPSIZE: 1608; COMPONENTTYPE: 4; FNAPPROVALRESUG: B:i(GREEN); FNCANCELLATIONG: 0:Žg—p‰Â; FNENVIRONMANTRG: 1:gpL(K§ÎÛO); FNLEADFREETHET1GT2GMCTH1: 2_2_N; GANSWERREV: 8; GCOUNT: 1; INSTANCENAME: cmp141; MAKER: PANASONIC; MAXGCOUNT: 1; MOUNTINGFORMSMD: SMD; NOMINALRESISTAN: 1K; OUMECLASSIFICATION: \ÊÀpÅèïRí; OUMEMAKER: YGO ƒ„ƒQƒI; OUMEMAKERKATAMEI: RC0402FR-071KL; PMPRODUCTSTYPEG: HD1; POWERRATING: 63m; QUADMODEL: RES_1K; RESISTANCETOLER: F; SAVEAREA0: -588,-4192,15498,7584; SAVECOUNT: 0; SIZECODESMD: 1005; UPDATETIME: 09:21:07; VAL1: 1.78k(F); VAL2: 63mW; VAL3: ERJ2RKF1781X
R83 = R: ADSMODELNAME: s_RC0402FR_071KL; ALLGREEN: 0:O[; CDMASTERCADCELG: KC0005; CHIPSIZE: 1608; COMPONENTTYPE: 4; FNAPPROVALRESUG: B:i(GREEN); FNCANCELLATIONG: 0:Žg—p‰Â; FNENVIRONMANTRG: 1:gpL(K§ÎÛO); FNLEADFREETHET1GT2GMCTH1: 2_2_N; GANSWERREV: 8; GCOUNT: 1; INSTANCENAME: cmp222; MAKER: PANASONIC; MAXGCOUNT: 1; MOUNTINGFORMSMD: SMD; NOMINALRESISTAN: 1K; OUMECLASSIFICATION: \ÊÀpÅèïRí; OUMEMAKER: YGO ƒ„ƒQƒI; OUMEMAKERKATAMEI: RC0402FR-071KL; PMPRODUCTSTYPEG: HD1; POWERRATING: 63m; QUADMODEL: RES_1K; RESISTANCETOLER: F; SAVEAREA0: -588,-4192,15498,7584; SAVECOUNT: 0; SIZECODESMD: 1005; UPDATETIME: 09:21:07; VAL1: 3.57k(F); VAL2: 63mW; VAL3: ERJ2RKF3571X
R85 = R: ADSMODELNAME: s_RC0402FR_071KL; ALLGREEN: 0:O[; CDMASTERCADCELG: KC0005; CHIPSIZE: 1608; COMPONENTTYPE: 4; FNAPPROVALRESUG: B:i(GREEN); FNCANCELLATIONG: 0:Žg—p‰Â; FNENVIRONMANTRG: 1:gpL(K§ÎÛO); FNLEADFREETHET1GT2GMCTH1: 2_2_N; GANSWERREV: 8; GCOUNT: 1; INSTANCENAME: cmp218; MAKER: KOA; MAXGCOUNT: 1; MOUNTINGFORMSMD: SMD; NOMINALRESISTAN: 1K; OUMECLASSIFICATION: \ÊÀpÅèïRí; OUMEMAKER: YGO ƒ„ƒQƒI; OUMEMAKERKATAMEI: RC0402FR-071KL; PMPRODUCTSTYPEG: HD1; POWERRATING: 63m; QUADMODEL: RES_1K; RESISTANCETOLER: F; SAVEAREA0: -588,-4192,15498,7584; SAVECOUNT: 0; SIZECODESMD: 1005; UPDATETIME: 09:21:07; VAL1: 1k(J); VAL2: 63mW; VAL3: RK73K1ETP102J
R86 = R: ADSCNVFLAG: ON; ADSCOMPONENTNAME: R_1608; ADSMODELNAME: s_RC0402FR_071KL; ALLGREEN: 0:O[; CDMASTERCADCELG: KC0005; CHIPSIZE: 1608; COMPONENTTYPE: 4; FNAPPROVALRESUG: B:i(GREEN); FNCANCELLATIONG: 0:Žg—p‰Â; FNENVIRONMANTRG: 1:gpL(K§ÎÛO); FNLEADFREETHET1GT2GMCTH1: 2_2_N; GANSWERREV: 8; GCOUNT: 1; ICX_PART_MODEL: RES_1.74K; INSTANCENAME: cmp140; MAKER: PANASONIC; MAXGCOUNT: 1; MOUNTINGFORMSMD: SMD; NOMINALRESISTAN: 1K; OUMECLASSIFICATION: \ÊÀpÅèïRí; OUMEMAKER: YGO ƒ„ƒQƒI; OUMEMAKERKATAMEI: RC0402FR-071KL; PMPRODUCTSTYPEG: HD1; POWERRATING: 63m; QUADMODEL: RES_1K; RESISTANCETOLER: F; SAVEAREA0: -588,-4192,15498,7584; SAVECOUNT: 0; SIZECODESMD: 1005; SQ_PART_MODEL: RES_1.74K; UPDATETIME: 09:21:07; VAL1: 1.78k(F); VAL2: 63mW; VAL3: ERJ2RKF1781X
R87 = R: ADSMODELNAME: s_RC0402FR_071KL; ALLGREEN: 0:O[; CDMASTERCADCELG: KC0005; CHIPSIZE: 1608; COMPONENTTYPE: 4; FNAPPROVALRESUG: B:i(GREEN); FNCANCELLATIONG: 0:Žg—p‰Â; FNENVIRONMANTRG: 1:gpL(K§ÎÛO); FNLEADFREETHET1GT2GMCTH1: 2_2_N; GANSWERREV: 8; GCOUNT: 1; INSTANCENAME: cmp228; MAKER: PANASONIC; MAXGCOUNT: 1; MOUNTINGFORMSMD: SMD; NOMINALRESISTAN: 1K; OUMECLASSIFICATION: \ÊÀpÅèïRí; OUMEMAKER: YGO ƒ„ƒQƒI; OUMEMAKERKATAMEI: RC0402FR-071KL; PMPRODUCTSTYPEG: HD1; POWERRATING: 63m; QUADMODEL: RES_1K; RESISTANCETOLER: F; SAVEAREA0: -588,-4192,15498,7584; SAVECOUNT: 0; SIZECODESMD: 1005; UPDATETIME: 09:21:07; VAL1: 3.57k(F); VAL2: 63mW; VAL3: ERJ2RKF3571X
R108 = R: ADSMODELNAME: s_RK73H2BTTD6R80F; CDMASTERCADCELG: DR901A; CHIPSIZE: 3216; COMPONENTTYPE: 4; FNLEADFREETHET1GT2GMCTH1: 3_1_N; GCOUNT: 1; INSTANCENAME: cmp224; MAKER: BOURNS; MAXGCOUNT: 1; MOUNTINGFORMSMD: SMD; NOMINALRESISTAN: 6.8; OUMECLASSIFICATION: \ÊÀpÅèïRí; OUMEMAKER: KOA R[A; OUMEMAKERKATAMEI: RK73H2BTTD6R80F; POWERRATING: 125m; QUADMODEL: RES_6.8; RESISTANCETOLER: F; SAVEAREA0: -588,-4192,15498,7584; SAVECOUNT: 0; SIZECODESMD: 3216; UPDATETIME: 09:21:07; VAL1: 5.11(F); VAL2: 500mW; VAL3: CRM1206-FX-5R11ELF
R109 = R: ADSMODELNAME: s_RK73H2BTTD6R80F; CDMASTERCADCELG: DR901A; CHIPSIZE: 3216; COMPONENTTYPE: 4; FNLEADFREETHET1GT2GMCTH1: 3_1_N; GCOUNT: 1; INSTANCENAME: cmp227; MAKER: BOURNS; MAXGCOUNT: 1; MOUNTINGFORMSMD: SMD; NOMINALRESISTAN: 6.8; OUMECLASSIFICATION: \ÊÀpÅèïRí; OUMEMAKER: KOA R[A; OUMEMAKERKATAMEI: RK73H2BTTD6R80F; POWERRATING: 125m; QUADMODEL: RES_6.8; RESISTANCETOLER: F; SAVEAREA0: -588,-4192,15498,7584; SAVECOUNT: 0; SIZECODESMD: 3216; UPDATETIME: 09:21:07; VAL1: 5.11(F); VAL2: 500mW; VAL3: CRM1206-FX-5R11ELF
R121 = R: ADSMODELNAME: s_RC0402FR_071KL; ALLGREEN: 0:O[; CDMASTERCADCELG: KC0005; CHIPSIZE: 1608; COMPONENTTYPE: 4; FNAPPROVALRESUG: B:i(GREEN); FNCANCELLATIONG: 0:Žg—p‰Â; FNENVIRONMANTRG: 1:gpL(K§ÎÛO); FNLEADFREETHET1GT2GMCTH1: 2_2_N; GANSWERREV: 8; GCOUNT: 1; INSTANCENAME: cmp146; MAKER: PANASONIC; MAXGCOUNT: 1; MOUNTINGFORMSMD: SMD; NOMINALRESISTAN: 1K; OUMECLASSIFICATION: \ÊÀpÅèïRí; OUMEMAKER: YGO ƒ„ƒQƒI; OUMEMAKERKATAMEI: RC0402FR-071KL; PMPRODUCTSTYPEG: HD1; POWERRATING: 63m; QUADMODEL: RES_1K; RESISTANCETOLER: F; SAVEAREA0: -588,-4192,15498,7584; SAVECOUNT: 0; SIZECODESMD: 1005; UPDATETIME: 09:21:07; VAL1: 1(J); VAL2: 63mW; VAL3: ERJ2GEJ1R0X
R172 = R: ADSMODELNAME: s_RC0402FR_071KL; ALLGREEN: 0:O[; CDMASTERCADCELG: KC0005; CHIPSIZE: 1608; COMPONENTTYPE: 4; FNAPPROVALRESUG: B:i(GREEN); FNCANCELLATIONG: 0:Žg—p‰Â; FNENVIRONMANTRG: 1:gpL(K§ÎÛO); FNLEADFREETHET1GT2GMCTH1: 2_2_N; GANSWERREV: 8; GCOUNT: 1; INSTANCENAME: cmp154; MAKER: KOA; MAXGCOUNT: 1; MOUNTINGFORMSMD: SMD; NOMINALRESISTAN: 1K; OUMECLASSIFICATION: \ÊÀpÅèïRí; OUMEMAKER: YGO ƒ„ƒQƒI; OUMEMAKERKATAMEI: RC0402FR-071KL; PMPRODUCTSTYPEG: HD1; POWERRATING: 63m; QUADMODEL: RES_1K; RESISTANCETOLER: F; SAVEAREA0: -588,-4192,15498,7584; SAVECOUNT: 0; SIZECODESMD: 1005; UPDATETIME: 09:21:07; VAL1: 100(J); VAL2: 63mW; VAL3: RK73K1ETP101J
R173 = R: ADSMODELNAME: s_RC0402FR_071KL; ALLGREEN: 0:O[; CDMASTERCADCELG: KC0005; CHIPSIZE: 1608; COMPONENTTYPE: 4; FNAPPROVALRESUG: B:i(GREEN); FNCANCELLATIONG: 0:Žg—p‰Â; FNENVIRONMANTRG: 1:gpL(K§ÎÛO); FNLEADFREETHET1GT2GMCTH1: 2_2_N; GANSWERREV: 8; GCOUNT: 1; INSTANCENAME: cmp155; MAKER: KOA; MAXGCOUNT: 1; MOUNTINGFORMSMD: SMD; NOMINALRESISTAN: 1K; OUMECLASSIFICATION: \ÊÀpÅèïRí; OUMEMAKER: YGO ƒ„ƒQƒI; OUMEMAKERKATAMEI: RC0402FR-071KL; PMPRODUCTSTYPEG: HD1; POWERRATING: 63m; QUADMODEL: RES_1K; RESISTANCETOLER: F; SAVEAREA0: -588,-4192,15498,7584; SAVECOUNT: 0; SIZECODESMD: 1005; UPDATETIME: 09:21:07; VAL1: 100(J); VAL2: 63mW; VAL3: RK73K1ETP101J
T2 = T2Q: ADSMODELNAME: s_CT332920S_46; AUTHOR: sptcae13; CDMASTERCADCELG: DT0334; COMP: PRT_7; COMPONENTTYPE: 4; DATE: 2024/01/31; FNLEADFREETHET1GT2GMCTH1: N_N_N; GCOUNT: 1; INPUTVOLTAGE: 99.999K; INSTANCENAME: cmp26; MAINOUTPUTVOLTA: 99.999K; MAKER: PONY; MAXGCOUNT: 1; MAXRATEDCURREN1: 0; MOUNTINGFORMSMD: DIP; OUMECLASSIFICATION: “dŒ¹ƒgƒ‰ƒ“ƒX; OUMEMAKER: TDK ‚s‚c‚j; OUMEMAKERKATAMEI: CT332920S-46; OUMEPARTTYPE: T; PRIMARYINDUCTAN: 0; RATEDFREQ: 0; RATEDOUTPUT: 99.999K; RATEDOUTPUTVOLT: 0; SAVECOUNT: 0; TIME: 13:58:25; UPDATEDATE: 2024/01/31; UPDATETIME: 13:58:25; UPDATEUSER: sptcae13; VAL1: 1:200; VAL3: P009-203
T3 = T2Q: ADSMODELNAME: s_CT332920S_46; AUTHOR: sptcae13; CDMASTERCADCELG: DT0334; COMP: PRT_7; COMPONENTTYPE: 4; DATE: 2024/01/31; FNLEADFREETHET1GT2GMCTH1: N_N_N; GCOUNT: 1; INPUTVOLTAGE: 99.999K; INSTANCENAME: cmp41; MAINOUTPUTVOLTA: 99.999K; MAKER: PONY; MAXGCOUNT: 1; MAXRATEDCURREN1: 0; MOUNTINGFORMSMD: DIP; OUMECLASSIFICATION: “dŒ¹ƒgƒ‰ƒ“ƒX; OUMEMAKER: TDK ‚s‚c‚j; OUMEMAKERKATAMEI: CT332920S-46; OUMEPARTTYPE: T; PRIMARYINDUCTAN: 0; RATEDFREQ: 0; RATEDOUTPUT: 99.999K; RATEDOUTPUTVOLT: 0; SAVECOUNT: 0; TIME: 13:58:25; UPDATEDATE: 2024/01/31; UPDATETIME: 13:58:25; UPDATEUSER: sptcae13; VAL1: 1:200; VAL3: P009-203
TP1 = TP: AUTHOR: sptcae13; COMP: PRT_44; COMPONENTTYPE: 4; DATE: 2024/01/31; INSTANCENAME: cmp186; MAKER: MAC8; TIME: 13:58:25; UPDATEDATE: 2024/01/31; UPDATETIME: 13:58:25; UPDATEUSER: sptcae13; VAL3: HK-2-S
TP2 = TP: AUTHOR: sptcae13; COMP: PRT_44; COMPONENTTYPE: 4; DATE: 2024/01/31; INSTANCENAME: cmp187; MAKER: MAC8; TIME: 13:58:25; UPDATEDATE: 2024/01/31; UPDATETIME: 13:58:25; UPDATEUSER: sptcae13; VAL3: HK-2-S
TP3 = TP: AUTHOR: sptcae13; COMP: PRT_44; COMPONENTTYPE: 4; DATE: 2024/01/31; INSTANCENAME: cmp188; MAKER: MAC8; TIME: 13:58:25; UPDATEDATE: 2024/01/31; UPDATETIME: 13:58:25; UPDATEUSER: sptcae13; VAL3: HK-2-S
TP4 = TP: AUTHOR: sptcae13; COMP: PRT_44; COMPONENTTYPE: 4; DATE: 2024/01/31; INSTANCENAME: cmp189; MAKER: MAC8; TIME: 13:58:25; UPDATEDATE: 2024/01/31; UPDATETIME: 13:58:25; UPDATEUSER: sptcae13; VAL3: HK-2-S
TP44 = TP: AUTHOR: sptcae13; COMP: PRT_44; COMPONENTTYPE: 4; DATE: 2024/01/31; INSTANCENAME: cmp195; MAKER: MAC8; TIME: 13:58:25; UPDATEDATE: 2024/01/31; UPDATETIME: 13:58:25; UPDATEUSER: sptcae13; VAL3: HK-2-S
U?#7 = WAKU_DEF100: COMPONENTTYPE: 2; DATE: 2024/02/05; DESIGNED: TOSHIBA; DRAWINGNUMBER: RD240-SCHEMATIC-01; FUNCTION: PFC - Switching; INSTANCENAME: cmp236; PAGENUMBER: 2; REVISION: 01; SHEETNUMBER: 2/9; SHTSAVECOUNT: 42; TITLE: 1.6 kW Server Power Supply / (Upgraded); UPDATEDATE: 2024/02/07; UPDATETIME: 10:56:58; UPDATEUSER: t5459927

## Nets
VCC12R0_1: IC2.1 IC2.8 R83.2 R87.2 R121.1 ; also on sheet 2 6 7 9
CSA: D13.C D33.C R7.2 R87.1 TP2.1 ; also on sheet 7
CSB: D12.C D31.C R8.2 R83.1 TP1.1 ; also on sheet 7
GDA: C81.2 IC2.2 ; also on sheet 7
GDB: C80.2 IC2.4 ; also on sheet 7
PFC_OUT: C1.2 C7.2 D1.C D2.C D3.1 TP44.1 ; also on sheet 2 6 7
PFC_VIN: D8.C D9.C ; also on sheet 7
PN: C1.1 C7.1 C34.1 C35.1 C36.1 C37.1 C62.1 C80.1 C81.1 C82.1 C83.1 D3.4 IC2.3 Q1.S Q2.S R7.1 R8.1 R71.1 R73.1 T2.2 T3.2 ; also on sheet 2 3 6 7 9
SIG6: D3.3 D9.A L2.1 ; also on sheet 9
SIG8: D3.2 D8.A L1.1 ; also on sheet 9
SIG11: D2.A L2.2 T2.4
SIG12: D1.A L1.2 T3.4
SIG15: D12.A R81.2 T2.1
SIG16: C34.2 R81.1
SIG18: Q2.D T2.3
SIG20: D13.A R85.2 T3.1
SIG21: C36.2 R85.1
SIG22: Q1.D T3.3
SIG23: FB1.1 R71.2 R72.2 R108.2
SIG24: C35.2 D31.A R82.2 R172.2
SIG25: C37.2 D33.A R86.2 R173.2
SIG27: FB2.1 R73.2 R74.2 R109.2
SIG30: D32.C D38.A D39.C IC2.7 R86.1
SIG100: D36.C R72.1
SIG101: D37.A R108.1
SIG102: D30.C D36.A D37.C IC2.5 R82.1
SIG104: C62.2 C82.2 C83.2 IC2.6 R121.2
SIG105: D39.A R109.1
SIG106: D38.C R74.1
SIGN254: D30.A R172.1
SIGN255: D32.A R173.1
SIGN266: FB1.2 Q2.G TP3.1
SIGN267: FB2.2 Q1.G TP4.1

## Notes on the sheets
sheet 8
- for current measurement
